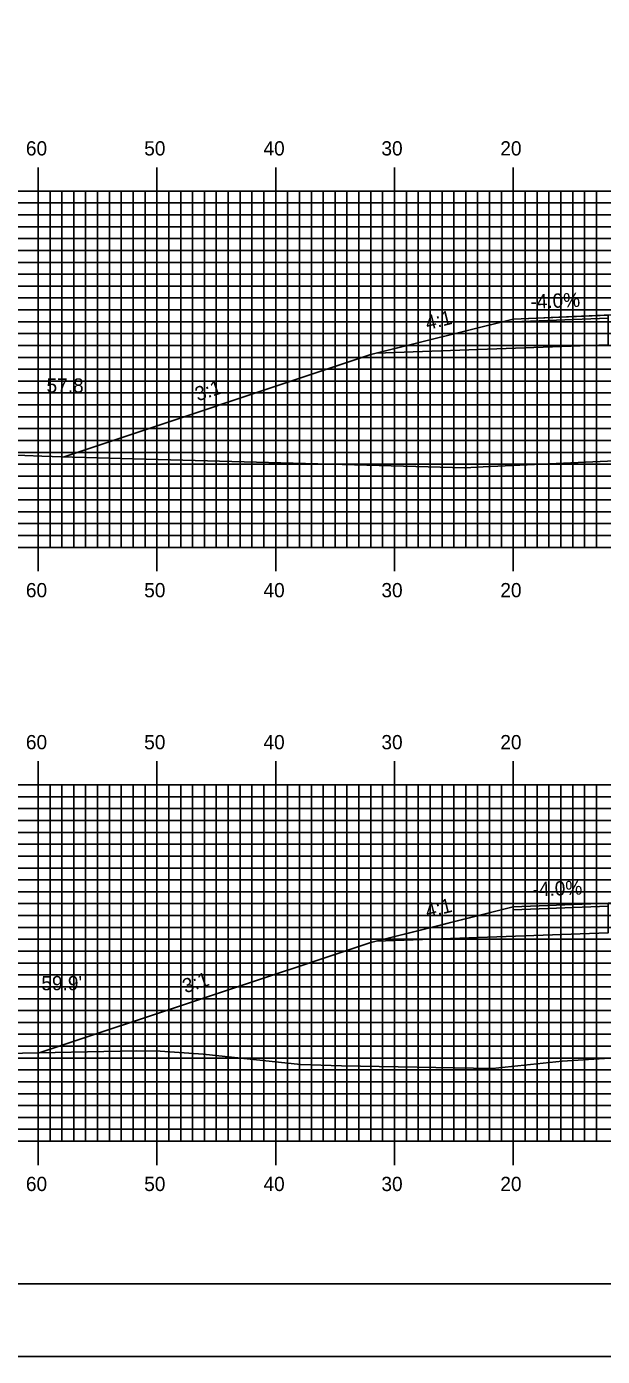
# Model space of a CAD drawing. Extents: x 1762972 to 1763315, y 442591 to 442811.
# Drawn here: x 1763076.3 to 1763124.8, y 442590.5 to 442702.5 of the extents above; entities that cross this region are included whole.
import ezdxf

# ---------------------------------------------------------------- set-up
doc = ezdxf.new("R2010")
doc.units = 0
for name, color, linetype in [('ANNOTATION', 7, 'Continuous'), ('BORDER', 7, 'Continuous'), ('D_Roadway_Centerline', 7, 'Continuous'), ('D_Roadway_Edge_Shoulder', 7, 'Continuous'), ('D_Roadway_SlopeLines', 7, 'Continuous'), ('D_Roadway_SubGrade', 7, 'Continuous'), ('D_Text_Standard', 7, 'Continuous'), ('H_V ANNOTATION', 7, 'Continuous'), ('MAJOR', 7, 'Continuous'), ('MINOR', 7, 'Continuous'), ('PLOT BOUNDARY', 7, 'Continuous'), ('S_Roadway_Centerline', 7, 'Continuous')]:
    doc.layers.add(name, color=color, linetype=linetype)

msp = doc.modelspace()

# ---------------------------------------------------------------- linework, layer by layer
at = {"layer": 'BORDER'}
msp.add_lwpolyline([(1762987.69, 442596.67), (1763307.69, 442596.67), (1763307.69, 442806.67), (1762987.69, 442806.67)], close=True, dxfattribs=at)
at = {"layer": 'D_Roadway_Centerline'}
for points in [[(1763079.48, 442666.3), (1763079.48, 442666.3), (1763105.29, 442674.9), (1763105.76, 442675.02), (1763117.29, 442677.9), (1763117.29, 442677.9), (1763117.3, 442677.9), (1763124.95, 442678.21), (1763125.29, 442678.22), (1763125.84, 442678.24), (1763137.29, 442678.66), (1763147.6, 442679.03), (1763149.29, 442679.09), (1763150.49, 442679.04), (1763157.29, 442678.77), (1763157.29, 442678.77), (1763166.47, 442676.47), (1763167.47, 442676.22), (1763169.29, 442675.77), (1763173.61, 442674.33), (1763185.68, 442670.3)], [(1763077.39, 442616.1), (1763105.29, 442625.4), (1763105.29, 442625.4), (1763105.4, 442625.43), (1763105.76, 442625.52), (1763105.76, 442625.52), (1763110.16, 442626.62), (1763117.29, 442628.4), (1763117.29, 442628.4), (1763125.29, 442628.72), (1763137.29, 442629.16), (1763137.29, 442629.16), (1763142.07, 442629.33), (1763149.29, 442629.59), (1763149.3, 442629.59), (1763157.29, 442629.27), (1763167.47, 442626.72), (1763168.66, 442626.42), (1763169.29, 442626.27), (1763169.3, 442626.27), (1763173.13, 442624.99), (1763188.08, 442620.01), (1763188.09, 442620)]]:
    msp.add_lwpolyline(points, dxfattribs=at)
at = {"layer": 'D_Roadway_Edge_Shoulder'}
for points in [[(1763125.29, 442678.22), (1763117.29, 442677.9), (1763117.29, 442677.65), (1763125.29, 442677.97)], [(1763125.29, 442628.72), (1763117.29, 442628.4), (1763117.29, 442628.15), (1763125.29, 442628.47)]]:
    msp.add_lwpolyline(points, close=True, dxfattribs=at)
at = {"layer": 'D_Roadway_SlopeLines'}
for points in [[(1763117.29, 442677.9), (1763105.29, 442674.9), (1763079.48, 442666.3)], [(1763117.29, 442628.4), (1763105.29, 442625.4), (1763077.39, 442616.1)]]:
    msp.add_lwpolyline(points, dxfattribs=at)
at = {"layer": 'D_Roadway_SubGrade'}
for points in [[(1763117.29, 442677.65), (1763125.29, 442677.97), (1763125.29, 442677.56), (1763125.29, 442675.72), (1763105.76, 442675.02), (1763117.29, 442677.9)], [(1763117.29, 442628.15), (1763125.29, 442628.47), (1763125.29, 442628.06), (1763125.29, 442626.22), (1763105.76, 442625.52), (1763117.29, 442628.4)]]:
    msp.add_lwpolyline(points, close=True, dxfattribs=at)
at = {"layer": 'MAJOR'}
for p, q in [((1763077.29, 442690.67), (1763077.29, 442688.67)), ((1763087.29, 442690.67), (1763087.29, 442688.67)), ((1763097.29, 442690.67), (1763097.29, 442688.67)), ((1763107.29, 442690.67), (1763107.29, 442688.67)), ((1763117.29, 442690.67), (1763117.29, 442688.67)), ((1762997.29, 442688.67), (1763277.29, 442688.67)), ((1762997.29, 442688.67), (1763277.29, 442688.67)), ((1763077.29, 442658.67), (1763077.29, 442688.67)), ((1763087.29, 442658.67), (1763087.29, 442688.67)), ((1763097.29, 442658.67), (1763097.29, 442688.67)), ((1763107.29, 442658.67), (1763107.29, 442688.67)), ((1763117.29, 442658.67), (1763117.29, 442688.67)), ((1762997.29, 442683.67), (1763277.29, 442683.67)), ((1762997.29, 442678.67), (1763277.29, 442678.67)), ((1762997.29, 442673.67), (1763277.29, 442673.67)), ((1762997.29, 442668.67), (1763277.29, 442668.67)), ((1762997.29, 442663.67), (1763277.29, 442663.67)), ((1762997.29, 442658.67), (1763277.29, 442658.67)), ((1762997.29, 442658.67), (1763277.29, 442658.67)), ((1763077.29, 442656.66), (1763077.29, 442658.67)), ((1763087.29, 442656.66), (1763087.29, 442658.67)), ((1763097.29, 442656.66), (1763097.29, 442658.67)), ((1763107.29, 442656.66), (1763107.29, 442658.67)), ((1763117.29, 442656.66), (1763117.29, 442658.67)), ((1763077.29, 442640.67), (1763077.29, 442638.67)), ((1763087.29, 442640.67), (1763087.29, 442638.67)), ((1763097.29, 442640.67), (1763097.29, 442638.67)), ((1763107.29, 442640.67), (1763107.29, 442638.67)), ((1763117.29, 442640.67), (1763117.29, 442638.67)), ((1762997.29, 442638.67), (1763277.29, 442638.67)), ((1762997.29, 442638.67), (1763277.29, 442638.67)), ((1763077.29, 442608.67), (1763077.29, 442638.67)), ((1763087.29, 442608.67), (1763087.29, 442638.67)), ((1763097.29, 442608.67), (1763097.29, 442638.67)), ((1763107.29, 442608.67), (1763107.29, 442638.67)), ((1763117.29, 442608.67), (1763117.29, 442638.67)), ((1762997.29, 442633.67), (1763277.29, 442633.67)), ((1762997.29, 442628.67), (1763277.29, 442628.67)), ((1762997.29, 442623.67), (1763277.29, 442623.67)), ((1762997.29, 442618.67), (1763277.29, 442618.67)), ((1762997.29, 442613.67), (1763277.29, 442613.67)), ((1762997.29, 442608.67), (1763277.29, 442608.67)), ((1762997.29, 442608.67), (1763277.29, 442608.67)), ((1763077.29, 442606.66), (1763077.29, 442608.67)), ((1763087.29, 442606.66), (1763087.29, 442608.67)), ((1763097.29, 442606.66), (1763097.29, 442608.67)), ((1763107.29, 442606.66), (1763107.29, 442608.67)), ((1763117.29, 442606.66), (1763117.29, 442608.67))]:
    msp.add_line(p, q, dxfattribs=at)
at = {"layer": 'MINOR'}
for p, q in [((1763078.29, 442658.67), (1763078.29, 442688.67)), ((1763079.29, 442658.67), (1763079.29, 442688.67)), ((1763080.29, 442658.67), (1763080.29, 442688.67)), ((1763081.29, 442658.67), (1763081.29, 442688.67)), ((1763082.29, 442658.67), (1763082.29, 442688.67)), ((1763083.29, 442658.67), (1763083.29, 442688.67)), ((1763084.29, 442658.67), (1763084.29, 442688.67)), ((1763085.29, 442658.67), (1763085.29, 442688.67)), ((1763086.29, 442658.67), (1763086.29, 442688.67)), ((1763088.29, 442658.67), (1763088.29, 442688.67)), ((1763089.29, 442658.67), (1763089.29, 442688.67)), ((1763090.29, 442658.67), (1763090.29, 442688.67)), ((1763091.29, 442658.67), (1763091.29, 442688.67)), ((1763092.29, 442658.67), (1763092.29, 442688.67)), ((1763093.29, 442658.67), (1763093.29, 442688.67)), ((1763094.29, 442658.67), (1763094.29, 442688.67)), ((1763095.29, 442658.67), (1763095.29, 442688.67)), ((1763096.29, 442658.67), (1763096.29, 442688.67)), ((1763098.29, 442658.67), (1763098.29, 442688.67)), ((1763099.29, 442658.67), (1763099.29, 442688.67)), ((1763100.29, 442658.67), (1763100.29, 442688.67)), ((1763101.29, 442658.67), (1763101.29, 442688.67)), ((1763102.29, 442658.67), (1763102.29, 442688.67)), ((1763103.29, 442658.67), (1763103.29, 442688.67)), ((1763104.29, 442658.67), (1763104.29, 442688.67)), ((1763105.29, 442658.67), (1763105.29, 442688.67)), ((1763106.29, 442658.67), (1763106.29, 442688.67)), ((1763108.29, 442658.67), (1763108.29, 442688.67)), ((1763109.29, 442658.67), (1763109.29, 442688.67)), ((1763110.29, 442658.67), (1763110.29, 442688.67)), ((1763111.29, 442658.67), (1763111.29, 442688.67)), ((1763112.29, 442658.67), (1763112.29, 442688.67)), ((1763113.29, 442658.67), (1763113.29, 442688.67)), ((1763114.29, 442658.67), (1763114.29, 442688.67)), ((1763115.29, 442658.67), (1763115.29, 442688.67)), ((1763116.29, 442658.67), (1763116.29, 442688.67)), ((1763118.29, 442658.67), (1763118.29, 442688.67)), ((1763119.29, 442658.67), (1763119.29, 442688.67)), ((1763120.29, 442658.67), (1763120.29, 442688.67)), ((1763121.29, 442658.67), (1763121.29, 442688.67)), ((1763122.29, 442658.67), (1763122.29, 442688.67)), ((1763123.29, 442658.67), (1763123.29, 442688.67)), ((1763124.29, 442658.67), (1763124.29, 442688.67)), ((1762997.29, 442687.67), (1763277.29, 442687.67)), ((1762997.29, 442686.67), (1763277.29, 442686.67)), ((1762997.29, 442685.67), (1763277.29, 442685.67)), ((1762997.29, 442684.67), (1763277.29, 442684.67)), ((1762997.29, 442682.67), (1763277.29, 442682.67)), ((1762997.29, 442681.67), (1763277.29, 442681.67)), ((1762997.29, 442680.67), (1763277.29, 442680.67)), ((1762997.29, 442679.67), (1763277.29, 442679.67)), ((1762997.29, 442677.67), (1763277.29, 442677.67)), ((1762997.29, 442676.67), (1763277.29, 442676.67)), ((1762997.29, 442675.67), (1763277.29, 442675.67)), ((1762997.29, 442674.67), (1763277.29, 442674.67)), ((1762997.29, 442672.67), (1763277.29, 442672.67)), ((1762997.29, 442671.67), (1763277.29, 442671.67)), ((1762997.29, 442670.67), (1763277.29, 442670.67)), ((1762997.29, 442669.67), (1763277.29, 442669.67)), ((1762997.29, 442667.67), (1763277.29, 442667.67)), ((1762997.29, 442666.67), (1763277.29, 442666.67)), ((1762997.29, 442665.67), (1763277.29, 442665.67)), ((1762997.29, 442664.67), (1763277.29, 442664.67)), ((1762997.29, 442662.67), (1763277.29, 442662.67)), ((1762997.29, 442661.67), (1763277.29, 442661.67)), ((1762997.29, 442660.67), (1763277.29, 442660.67)), ((1762997.29, 442659.67), (1763277.29, 442659.67)), ((1763078.29, 442608.67), (1763078.29, 442638.67)), ((1763079.29, 442608.67), (1763079.29, 442638.67)), ((1763080.29, 442608.67), (1763080.29, 442638.67)), ((1763081.29, 442608.67), (1763081.29, 442638.67)), ((1763082.29, 442608.67), (1763082.29, 442638.67)), ((1763083.29, 442608.67), (1763083.29, 442638.67)), ((1763084.29, 442608.67), (1763084.29, 442638.67)), ((1763085.29, 442608.67), (1763085.29, 442638.67)), ((1763086.29, 442608.67), (1763086.29, 442638.67)), ((1763088.29, 442608.67), (1763088.29, 442638.67)), ((1763089.29, 442608.67), (1763089.29, 442638.67)), ((1763090.29, 442608.67), (1763090.29, 442638.67)), ((1763091.29, 442608.67), (1763091.29, 442638.67)), ((1763092.29, 442608.67), (1763092.29, 442638.67)), ((1763093.29, 442608.67), (1763093.29, 442638.67)), ((1763094.29, 442608.67), (1763094.29, 442638.67)), ((1763095.29, 442608.67), (1763095.29, 442638.67)), ((1763096.29, 442608.67), (1763096.29, 442638.67)), ((1763098.29, 442608.67), (1763098.29, 442638.67)), ((1763099.29, 442608.67), (1763099.29, 442638.67)), ((1763100.29, 442608.67), (1763100.29, 442638.67)), ((1763101.29, 442608.67), (1763101.29, 442638.67)), ((1763102.29, 442608.67), (1763102.29, 442638.67)), ((1763103.29, 442608.67), (1763103.29, 442638.67)), ((1763104.29, 442608.67), (1763104.29, 442638.67)), ((1763105.29, 442608.67), (1763105.29, 442638.67)), ((1763106.29, 442608.67), (1763106.29, 442638.67)), ((1763108.29, 442608.67), (1763108.29, 442638.67)), ((1763109.29, 442608.67), (1763109.29, 442638.67)), ((1763110.29, 442608.67), (1763110.29, 442638.67)), ((1763111.29, 442608.67), (1763111.29, 442638.67)), ((1763112.29, 442608.67), (1763112.29, 442638.67)), ((1763113.29, 442608.67), (1763113.29, 442638.67)), ((1763114.29, 442608.67), (1763114.29, 442638.67)), ((1763115.29, 442608.67), (1763115.29, 442638.67)), ((1763116.29, 442608.67), (1763116.29, 442638.67)), ((1763118.29, 442608.67), (1763118.29, 442638.67)), ((1763119.29, 442608.67), (1763119.29, 442638.67)), ((1763120.29, 442608.67), (1763120.29, 442638.67)), ((1763121.29, 442608.67), (1763121.29, 442638.67)), ((1763122.29, 442608.67), (1763122.29, 442638.67)), ((1763123.29, 442608.67), (1763123.29, 442638.67)), ((1763124.29, 442608.67), (1763124.29, 442638.67)), ((1762997.29, 442637.67), (1763277.29, 442637.67)), ((1762997.29, 442636.67), (1763277.29, 442636.67)), ((1762997.29, 442635.67), (1763277.29, 442635.67)), ((1762997.29, 442634.67), (1763277.29, 442634.67)), ((1762997.29, 442632.67), (1763277.29, 442632.67)), ((1762997.29, 442631.67), (1763277.29, 442631.67)), ((1762997.29, 442630.67), (1763277.29, 442630.67)), ((1762997.29, 442629.67), (1763277.29, 442629.67)), ((1762997.29, 442627.67), (1763277.29, 442627.67)), ((1762997.29, 442626.67), (1763277.29, 442626.67)), ((1762997.29, 442625.67), (1763277.29, 442625.67)), ((1762997.29, 442624.67), (1763277.29, 442624.67)), ((1762997.29, 442622.67), (1763277.29, 442622.67)), ((1762997.29, 442621.67), (1763277.29, 442621.67)), ((1762997.29, 442620.67), (1763277.29, 442620.67)), ((1762997.29, 442619.67), (1763277.29, 442619.67)), ((1762997.29, 442617.67), (1763277.29, 442617.67)), ((1762997.29, 442616.67), (1763277.29, 442616.67)), ((1762997.29, 442615.67), (1763277.29, 442615.67)), ((1762997.29, 442614.67), (1763277.29, 442614.67)), ((1762997.29, 442612.67), (1763277.29, 442612.67)), ((1762997.29, 442611.67), (1763277.29, 442611.67)), ((1762997.29, 442610.67), (1763277.29, 442610.67)), ((1762997.29, 442609.67), (1763277.29, 442609.67))]:
    msp.add_line(p, q, dxfattribs=at)
at = {"layer": 'PLOT BOUNDARY'}
msp.add_lwpolyline([(1762971.51, 442590.55), (1763311.51, 442590.55), (1763311.51, 442810.55), (1762971.51, 442810.55)], close=True, dxfattribs=at)
at = {"layer": 'S_Roadway_Centerline'}
for points in [[(1762997.29, 442665.43), (1763013.11, 442665.98), (1763021.07, 442666.09), (1763036.04, 442666.99), (1763038.16, 442667.04), (1763040.53, 442666.99), (1763044.59, 442666.73), (1763052.77, 442665.87), (1763057.54, 442666.14), (1763064.98, 442666.52), (1763076.16, 442666.41), (1763077.6, 442666.34), (1763080.19, 442666.28), (1763113.21, 442665.36), (1763114.75, 442665.44), (1763125.83, 442665.97), (1763131.53, 442666.32), (1763148.37, 442667.91), (1763150.54, 442668.16), (1763162.56, 442669.17), (1763168.92, 442669.48), (1763185.04, 442670.28), (1763188.37, 442670.4), (1763198.83, 442670.65)], [(1763074.61, 442616.05), (1763085.57, 442616.27), (1763087.55, 442616.24), (1763091.19, 442616), (1763099.37, 442615.12), (1763102.82, 442615.01), (1763115.53, 442614.78), (1763121.4, 442615.41), (1763135.67, 442616.3), (1763140.38, 442616.47), (1763154.21, 442617.61), (1763158.15, 442617.94), (1763159.41, 442618.06), (1763162.05, 442618.31), (1763171.51, 442619.25), (1763177.55, 442619.67), (1763184.04, 442619.67), (1763192.69, 442620.38)]]:
    msp.add_lwpolyline(points, dxfattribs=at)

# ---------------------------------------------------------------- texts
at = {"layer": 'ANNOTATION'}
for s, rotation, p in [('-4.0%', 2.2908, (1763118.75, 442678.76)), ('4:1', 14.0394, (1763110.06, 442676.96)), ('3:1', 18.4357, (1763090.73, 442670.96)), ('-4.0%', 2.2907, (1763118.93, 442629.27)), ('4:1', 14.0392, (1763110.06, 442627.46)), ('3:1', 18.4347, (1763089.68, 442621.11))]:
    msp.add_text(s, height=1.2, rotation=rotation, dxfattribs=at).set_placement(p)
at = {"layer": 'D_Text_Standard'}
for s, p in [("57.8'", (1763078, 442671.7)), ("59.9'", (1763077.56, 442621.38))]:
    msp.add_text(s, height=1.2, dxfattribs=at).set_placement(p)
at = {"layer": 'H_V ANNOTATION'}
for s, p in [('60', (1763076.26, 442691.67)), ('50', (1763086.22, 442691.67)), ('40', (1763096.26, 442691.67)), ('30', (1763106.19, 442691.67)), ('20', (1763116.2, 442691.67)), ('60', (1763076.26, 442654.47)), ('50', (1763086.22, 442654.47)), ('40', (1763096.26, 442654.47)), ('30', (1763106.19, 442654.47)), ('20', (1763116.2, 442654.47)), ('60', (1763076.26, 442641.67)), ('50', (1763086.22, 442641.67)), ('40', (1763096.26, 442641.67)), ('30', (1763106.19, 442641.67)), ('20', (1763116.2, 442641.67)), ('60', (1763076.26, 442604.47)), ('50', (1763086.22, 442604.47)), ('40', (1763096.26, 442604.47)), ('30', (1763106.19, 442604.47)), ('20', (1763116.2, 442604.47))]:
    msp.add_text(s, height=1.2, dxfattribs=at).set_placement(p)

doc.saveas('drawing.dxf')
